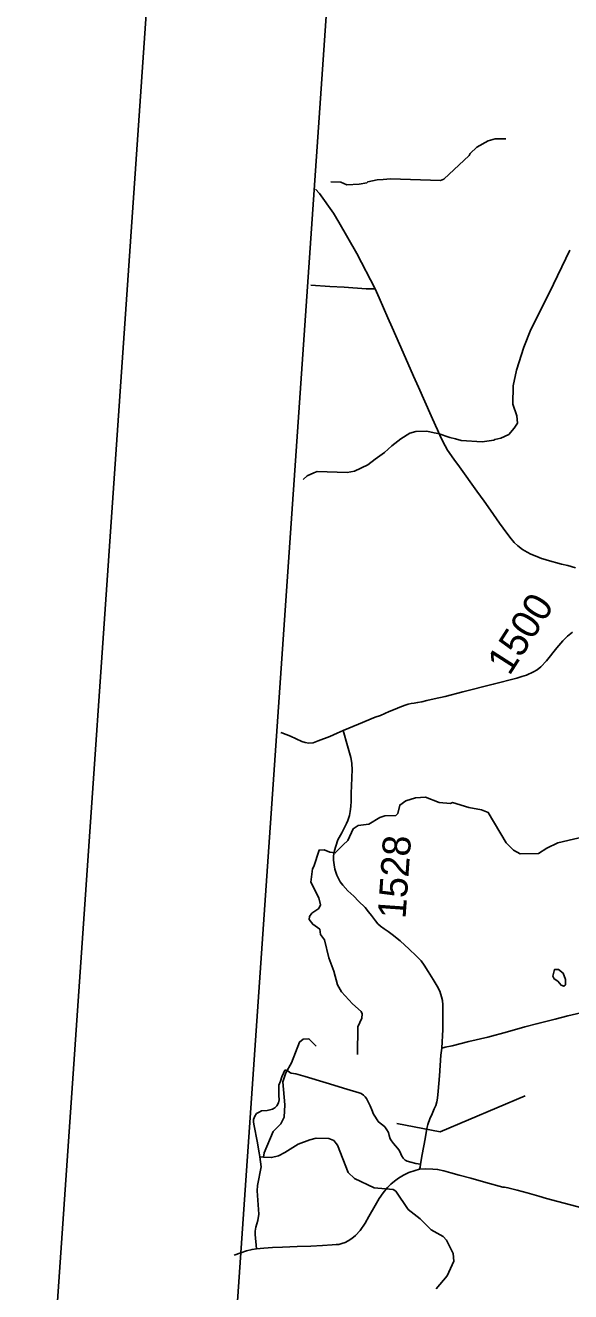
# Model space of a CAD drawing. Extents: x 2599057 to 2600057, y 728628 to 732947.
# Drawn here: x 2599056.6 to 2599143.3, y 731705.3 to 731906.7 of the extents above; entities that cross this region are included whole.
import ezdxf

# ---------------------------------------------------------------- set-up
doc = ezdxf.new("R2010")
doc.units = 0
for name, color, linetype in [('CTL Sheet Border CELL', 7, 'Continuous'), ('Old_Level_1', 7, 'Continuous'), ('Old_Level_29', 7, 'Continuous'), ('Old_Level_31', 7, 'Continuous'), ('Old_Level_32', 7, 'Continuous'), ('Old_Level_50', 7, 'Continuous'), ('Old_Level_59', 7, 'Continuous'), ('Old_Level_60', 7, 'Continuous')]:
    doc.layers.add(name, color=color, linetype=linetype)

msp = doc.modelspace()

# ---------------------------------------------------------------- linework, layer by layer
at = {"layer": 'CTL Sheet Border CELL'}
msp.add_lwpolyline([(2599146.23, 732931.19), (2599056.61, 731629.92), (2599967.49, 731567.19), (2600057.11, 732868.45)], close=True, dxfattribs=at)
at = {"layer": 'Old_Level_1'}
msp.add_line((2599108.17, 731962.68), (2599087.2, 731658.27), dxfattribs=at)
at = {"layer": 'Old_Level_29'}
for points in [[(2599112.2, 731864.77), (2599109.29, 731870.36), (2599106.45, 731875.37), (2599105.58, 731876.78), (2599103.35, 731879.93), (2599102.73, 731880.6)], [(2599144.04, 731820.42), (2599142.84, 731820.74), (2599141.84, 731820.99), (2599139.56, 731821.59), (2599139.2, 731821.7), (2599138.62, 731821.9), (2599137.89, 731822.18), (2599136.95, 731822.57), (2599136.35, 731822.87), (2599135.62, 731823.33), (2599134.85, 731823.91), (2599134.31, 731824.43), (2599133.61, 731825.25), (2599132.53, 731826.7), (2599131.96, 731827.51), (2599130.52, 731829.55), (2599129.51, 731830.98), (2599128.36, 731832.59), (2599125.59, 731836.48), (2599124.72, 731837.68), (2599123.69, 731839.1), (2599123.32, 731839.78), (2599123, 731840.39), (2599122.49, 731841.47), (2599122.09, 731842.32), (2599121.78, 731843.03), (2599121.09, 731844.56), (2599119.09, 731849.12), (2599118.32, 731850.86), (2599116.67, 731854.64), (2599114.89, 731858.62), (2599114.2, 731860.13), (2599112.83, 731863.31), (2599112.2, 731864.77)]]:
    msp.add_lwpolyline(points, dxfattribs=at)
at = {"layer": 'Old_Level_31'}
for p, q in [((2599105.69, 731774.53), (2599105.69, 731774.53)), ((2599113.11, 731731.96), (2599113.11, 731731.96))]:
    msp.add_line(p, q, dxfattribs=at)
msp.add_lwpolyline([(2599136.02, 731736.44), (2599122.52, 731730.72), (2599115.66, 731732)], dxfattribs=at)
at = {"layer": 'Old_Level_32'}
for points in [[(2599112.2, 731864.77), (2599111.62, 731864.76), (2599110.75, 731864.79), (2599107.26, 731865.01), (2599104.99, 731865.16), (2599101.99, 731865.35)], [(2599107.13, 731794.5), (2599109.55, 731795.53), (2599112.18, 731796.62), (2599113.07, 731796.93), (2599114.42, 731797.54), (2599115.37, 731797.93), (2599116.13, 731798.26), (2599116.57, 731798.4), (2599116.97, 731798.57), (2599117.46, 731798.71), (2599117.91, 731798.81), (2599118.39, 731798.88), (2599118.94, 731798.97), (2599119.6, 731799.11), (2599120.42, 731799.31), (2599121.6, 731799.57), (2599123.34, 731799.95), (2599126.11, 731800.66), (2599130.98, 731801.87), (2599134.7, 731802.86), (2599135.49, 731803.1), (2599136.27, 731803.34), (2599137.36, 731803.83), (2599137.95, 731804.17), (2599138.55, 731804.65), (2599139.42, 731805.58), (2599141.05, 731807.66), (2599142, 731808.78), (2599142.77, 731809.52), (2599143.56, 731810.18)], [(2599097.23, 731794.22), (2599097.37, 731794.17), (2599098.77, 731793.65), (2599100.54, 731792.77), (2599101.06, 731792.6), (2599101.68, 731792.51), (2599102.36, 731792.57), (2599103.15, 731792.87), (2599104.98, 731793.56), (2599106.15, 731794.1), (2599107.13, 731794.5)], [(2599107.13, 731794.5), (2599107.82, 731792.11), (2599108.34, 731790.23), (2599108.5, 731789.31), (2599108.55, 731788.19), (2599108.5, 731787.14), (2599108.42, 731785.54), (2599108.37, 731784.73), (2599108.37, 731783.3), (2599108.34, 731782.43), (2599108.25, 731781.66), (2599108.14, 731780.99), (2599107.87, 731780.2), (2599107.64, 731779.73), (2599106.9, 731778.25), (2599106.29, 731777.13), (2599105.93, 731776.13), (2599105.75, 731775.44), (2599105.59, 731774.6), (2599105.59, 731774.5)], [(2599105.59, 731774.5), (2599105.57, 731773.88), (2599105.69, 731773.14), (2599105.79, 731772.48), (2599106.1, 731771.52), (2599106.42, 731770.89), (2599106.65, 731770.47), (2599107.06, 731769.91), (2599107.87, 731769.04), (2599108.79, 731768.16), (2599109.58, 731767.38), (2599110.6, 731766.38), (2599111.14, 731765.7), (2599111.61, 731765.11), (2599112.26, 731764.25), (2599112.63, 731763.8), (2599113.03, 731763.41), (2599113.63, 731762.97), (2599114.29, 731762.54), (2599114.91, 731762.1), (2599116.17, 731761.08), (2599117.59, 731759.74), (2599118.71, 731758.68), (2599119.51, 731757.9), (2599120.01, 731757.21), (2599120.62, 731756.21), (2599121.43, 731754.9), (2599122.07, 731753.85), (2599122.47, 731753.05), (2599122.76, 731752.17), (2599122.89, 731751.58), (2599122.95, 731750.89), (2599122.96, 731750.16), (2599122.96, 731748.31), (2599122.93, 731746.95), (2599122.8, 731744.01)], [(2599122.8, 731744.01), (2599123.33, 731744.14), (2599124.42, 731744.37), (2599127.09, 731745.05), (2599130.09, 731745.77), (2599133.22, 731746.58), (2599135.97, 731747.39), (2599138.06, 731747.92), (2599140.82, 731748.62), (2599142.82, 731749.12), (2599145.8, 731749.84)], [(2599119.41, 731725.54), (2599119.65, 731727.07), (2599120.14, 731729.6), (2599120.41, 731731.21), (2599120.58, 731731.88), (2599120.88, 731732.79), (2599121.26, 731733.54), (2599121.58, 731734.33), (2599121.82, 731734.89), (2599121.99, 731735.45), (2599122.13, 731736.06), (2599122.21, 731737.15), (2599122.42, 731739.62), (2599122.66, 731742.9), (2599122.8, 731744.01)], [(2599093.37, 731712.09), (2599093.15, 731714.38), (2599093.14, 731714.91), (2599093.22, 731715.53), (2599093.53, 731716.59), (2599093.72, 731717.61), (2599093.47, 731721.31), (2599093.52, 731722.17), (2599094.06, 731725.15), (2599093.9, 731726.74), (2599093.78, 731727.38), (2599093.43, 731729.21), (2599092.95, 731731.64), (2599092.86, 731732.24), (2599092.88, 731732.68), (2599093.1, 731733.18), (2599093.37, 731733.6), (2599093.75, 731733.85), (2599094.16, 731734.03), (2599095.02, 731734.11), (2599095.47, 731734.18), (2599095.91, 731734.31), (2599096.27, 731734.52), (2599096.6, 731734.85), (2599096.84, 731735.33), (2599096.93, 731735.79), (2599096.9, 731736.48), (2599096.87, 731737.34), (2599096.9, 731738.12), (2599097.14, 731738.78), (2599097.35, 731739.47), (2599097.61, 731740.02), (2599097.85, 731740.5), (2599097.99, 731740.51), (2599098.32, 731740.39), (2599098.62, 731740.15), (2599098.83, 731740.02), (2599099.57, 731739.93), (2599101.1, 731739.51), (2599104.44, 731738.51), (2599107.71, 731737.47), (2599109.64, 731736.88), (2599110, 731736.77), (2599110.34, 731736.52), (2599110.61, 731736.28), (2599110.83, 731736), (2599111.1, 731735.49), (2599111.39, 731734.84), (2599111.65, 731734.21), (2599111.96, 731733.51), (2599112.23, 731733.05), (2599112.7, 731732.36), (2599113, 731732.06), (2599113.4, 731731.74), (2599113.72, 731731.48), (2599114.03, 731731.04), (2599114.32, 731730.59), (2599114.45, 731730.09), (2599114.61, 731729.59), (2599114.79, 731729.28), (2599115.13, 731728.82), (2599115.74, 731728.11), (2599115.97, 731727.86), (2599116.18, 731727.46), (2599116.38, 731726.91), (2599116.64, 731726.51), (2599116.99, 731726.17), (2599117.3, 731726.02), (2599117.86, 731725.87), (2599118.67, 731725.65), (2599119.41, 731725.54)], [(2599093.37, 731712.09), (2599094.49, 731712.21), (2599095.89, 731712.3), (2599097.45, 731712.35), (2599099.79, 731712.45), (2599101.99, 731712.52), (2599103.83, 731712.61), (2599105.35, 731712.7), (2599106.01, 731712.76), (2599106.45, 731712.79), (2599106.92, 731712.96), (2599107.42, 731713.11), (2599107.93, 731713.38), (2599108.49, 731713.72), (2599109.09, 731714.21), (2599109.83, 731714.99), (2599110.59, 731716.18), (2599111.17, 731717.25), (2599112.21, 731718.97), (2599112.84, 731720.07), (2599113.47, 731721), (2599114.17, 731721.87), (2599114.69, 731722.39), (2599115.25, 731722.87), (2599115.89, 731723.35), (2599116.71, 731723.82), (2599117.55, 731724.22), (2599118.56, 731724.55), (2599119.24, 731724.76)], [(2599119.24, 731724.76), (2599119.36, 731725.08), (2599119.41, 731725.54)], [(2599119.24, 731724.76), (2599120.22, 731724.82), (2599121.36, 731724.77), (2599122.11, 731724.72), (2599123.1, 731724.51), (2599124.21, 731724.18), (2599125.53, 731723.82), (2599127.42, 731723.32), (2599129.81, 731722.63), (2599132.51, 731721.9), (2599132.73, 731721.88), (2599133.31, 731721.8), (2599134.78, 731721.41), (2599136.35, 731720.99), (2599138.19, 731720.48), (2599139.45, 731720.11), (2599141.21, 731719.61), (2599144.25, 731718.81), (2599155.18, 731715.73), (2599159.71, 731714.5), (2599161.68, 731713.91)], [(2599089.79, 731711.09), (2599090.84, 731711.43), (2599091.75, 731711.77), (2599092.65, 731712.01), (2599093.37, 731712.09)]]:
    msp.add_lwpolyline(points, dxfattribs=at)
at = {"layer": 'Old_Level_50'}
msp.add_line((2599105.62, 731774.49), (2599105.62, 731774.49), dxfattribs=at)
at = {"layer": 'Old_Level_59'}
msp.add_line((2599094.48, 731726.66), (2599093.9, 731726.74), dxfattribs=at)
for points in [[(2599132.98, 731888.62), (2599131.29, 731888.64), (2599130.15, 731888.3), (2599128.35, 731887.32), (2599127.3, 731886.3), (2599127.12, 731885.98), (2599123.13, 731882.2), (2599122.58, 731882), (2599114.65, 731882.26), (2599113.48, 731882.15), (2599112.52, 731882.08), (2599111.03, 731881.81), (2599110.86, 731881.65), (2599109.68, 731881.43), (2599107.72, 731881.3), (2599106.77, 731881.73), (2599105.15, 731881.81)], [(2599143.13, 731870.91), (2599139.89, 731864.19), (2599136.93, 731858.29), (2599135.81, 731855.49), (2599134.68, 731851.85), (2599134.12, 731849.36), (2599134.07, 731846.45), (2599134.73, 731844.58), (2599134.84, 731843.4), (2599134.31, 731842.59), (2599133.43, 731841.62), (2599132.18, 731841.01), (2599131.21, 731840.82), (2599131.04, 731840.72), (2599129.22, 731840.42), (2599125.89, 731840.63), (2599124.96, 731840.9), (2599124.07, 731841.11), (2599122.19, 731841.76), (2599121.57, 731841.89), (2599120.41, 731842.12), (2599118.66, 731842.09), (2599117.69, 731841.8), (2599116.27, 731840.91), (2599114.84, 731839.8), (2599113.68, 731838.74), (2599112.19, 731837.69), (2599111.04, 731836.8), (2599108.92, 731835.77), (2599107.75, 731835.55), (2599102.98, 731835.72), (2599102.45, 731835.52), (2599101.41, 731835.01), (2599100.78, 731834.44)], [(2599139.46, 731775.83), (2599138.14, 731774.95), (2599135.26, 731774.92), (2599134.19, 731775.48), (2599133.02, 731776.65), (2599130.18, 731781.49), (2599129.09, 731781.93), (2599127.1, 731782.3), (2599124.5, 731783.05), (2599124.16, 731782.9), (2599122.37, 731783.09), (2599120.19, 731783.93), (2599118.6, 731783.83), (2599117.05, 731783.35), (2599116.11, 731782.67), (2599115.78, 731781.34), (2599115.49, 731781.02), (2599113.74, 731780.94), (2599112.94, 731780.7), (2599111.18, 731779.61), (2599109.48, 731779.41), (2599108.72, 731778.89), (2599107.87, 731777.03), (2599107.1, 731776.33), (2599105.87, 731775.05), (2599104.98, 731775.15), (2599104.09, 731775.53), (2599103.3, 731775.51), (2599102.47, 731772.87), (2599102.25, 731772.54)], [(2599155.32, 731770.99), (2599155.05, 731771), (2599154.47, 731771.8), (2599153.29, 731772.81), (2599152.36, 731774.37), (2599151.41, 731775.31), (2599149.26, 731776.64), (2599148.9, 731777.05), (2599147.3, 731777.92), (2599146.19, 731777.8), (2599141.25, 731776.64), (2599139.46, 731775.83)], [(2599103.52, 731762.08), (2599103.4, 731762.92), (2599102.27, 731763.7), (2599101.73, 731764.46), (2599101.75, 731764.96), (2599102.16, 731765.5), (2599103.25, 731766.23), (2599103.49, 731766.78), (2599103.23, 731767.91), (2599101.98, 731770.38), (2599102.25, 731772.54)], [(2599103.52, 731762.08), (2599104.16, 731761.21), (2599104.82, 731758.38), (2599105.65, 731756.27), (2599106.19, 731754.07), (2599106.87, 731752.97), (2599108.62, 731751.04), (2599110, 731749.85), (2599110.14, 731749.45), (2599110.06, 731748.79), (2599109.45, 731747.42), (2599109.4, 731743.01)], [(2599102.83, 731744.33), (2599101.68, 731745.5), (2599100.78, 731745.43), (2599100.16, 731744.96), (2599098.9, 731741.67), (2599098.01, 731740.09), (2599097.51, 731738.66), (2599097.86, 731735.01), (2599097.72, 731733.05), (2599097.22, 731731.96), (2599096, 731730.73), (2599094.56, 731727.34), (2599094.48, 731726.66)], [(2599121.92, 731705.72), (2599123.63, 731707.82), (2599124.7, 731710.11), (2599124.6, 731711.35), (2599123.53, 731713.47), (2599123.03, 731714.05), (2599121.12, 731715.09), (2599119.36, 731716.85), (2599117.47, 731718.35), (2599115.49, 731721.24), (2599115.05, 731721.54), (2599112.03, 731721.79), (2599108.93, 731723.29), (2599107.91, 731724.23), (2599106.23, 731728.56), (2599105.63, 731729.32), (2599104.85, 731729.63), (2599102.85, 731729.68), (2599101.82, 731729.44), (2599099.98, 731728.75), (2599097.86, 731727.4), (2599096.86, 731726.89), (2599095.75, 731726.6), (2599094.48, 731726.66)]]:
    msp.add_lwpolyline(points, dxfattribs=at)
at = {"layer": 'Old_Level_60'}
msp.add_lwpolyline([(2599142.45, 731754.1), (2599142.17, 731753.84), (2599141.75, 731754.02), (2599141.21, 731754.66), (2599140.64, 731755.02), (2599140.44, 731755.43), (2599140.71, 731756.53), (2599141.35, 731756.5), (2599142.06, 731755.91), (2599142.43, 731754.94), (2599142.45, 731754.1)], dxfattribs=at)

# ---------------------------------------------------------------- texts
at = {"layer": 'Old_Level_1'}
for s, height, rotation, p in [('1500', 4.509, 57.3831, (2599133.53, 731803.11)), ('1528', 4.446, 86.0601, (2599117.02, 731764.5))]:
    msp.add_text(s, height=height, rotation=rotation, dxfattribs=at).set_placement(p)

doc.saveas('drawing.dxf')
